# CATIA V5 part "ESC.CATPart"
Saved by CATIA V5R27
Part number: ESC
Revision: ANY
Definition: UNKNOWN
Nomenclature: ESC
Source: Unknown
Bounding box of the stored display mesh (mm): x 0 to 41, y 0 to 15.5, z -77 to 0
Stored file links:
  W:\AAE451\Git\AAE451_Team7\ESC.CATPart
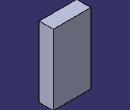
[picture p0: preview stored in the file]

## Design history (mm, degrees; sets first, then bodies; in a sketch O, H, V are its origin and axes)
Body1 "Boss-Extrude1" (main body)
  Solid1: solid without history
